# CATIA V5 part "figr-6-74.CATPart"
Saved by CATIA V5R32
Part number: Part1
Bounding box of the stored display mesh (mm): x 0 to 80, y -59 to 59, z -11 to 11
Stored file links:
  D:\PROJECTS\Project 2022\CATIA V5 6R 2022\Resources\Part Files\c06_catia_v5_6r2022_prt\figr-6-74.CATPart
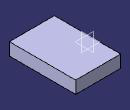
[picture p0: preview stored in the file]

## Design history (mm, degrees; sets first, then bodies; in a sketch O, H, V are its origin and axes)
Body1 (main body)
  Sketch1 on yz-plane, origin (0, 0, 0), H (0, 1, 0), V (0, 0, 1)
    line L1 (59, 11) -> (59, -11)
    line L2 (59, -11) -> (-59, -11)
    line L3 (-59, -11) -> (-59, 11)
    line L4 (-59, 11) -> (59, 11)
    vertical: L1 V, L3 V
    horizontal: L2 H, L4 H
    equidistance: L1 L3 O, L2 L4 O
  Pad1: profile Sketch1, direction (1, 0, 0), length 80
